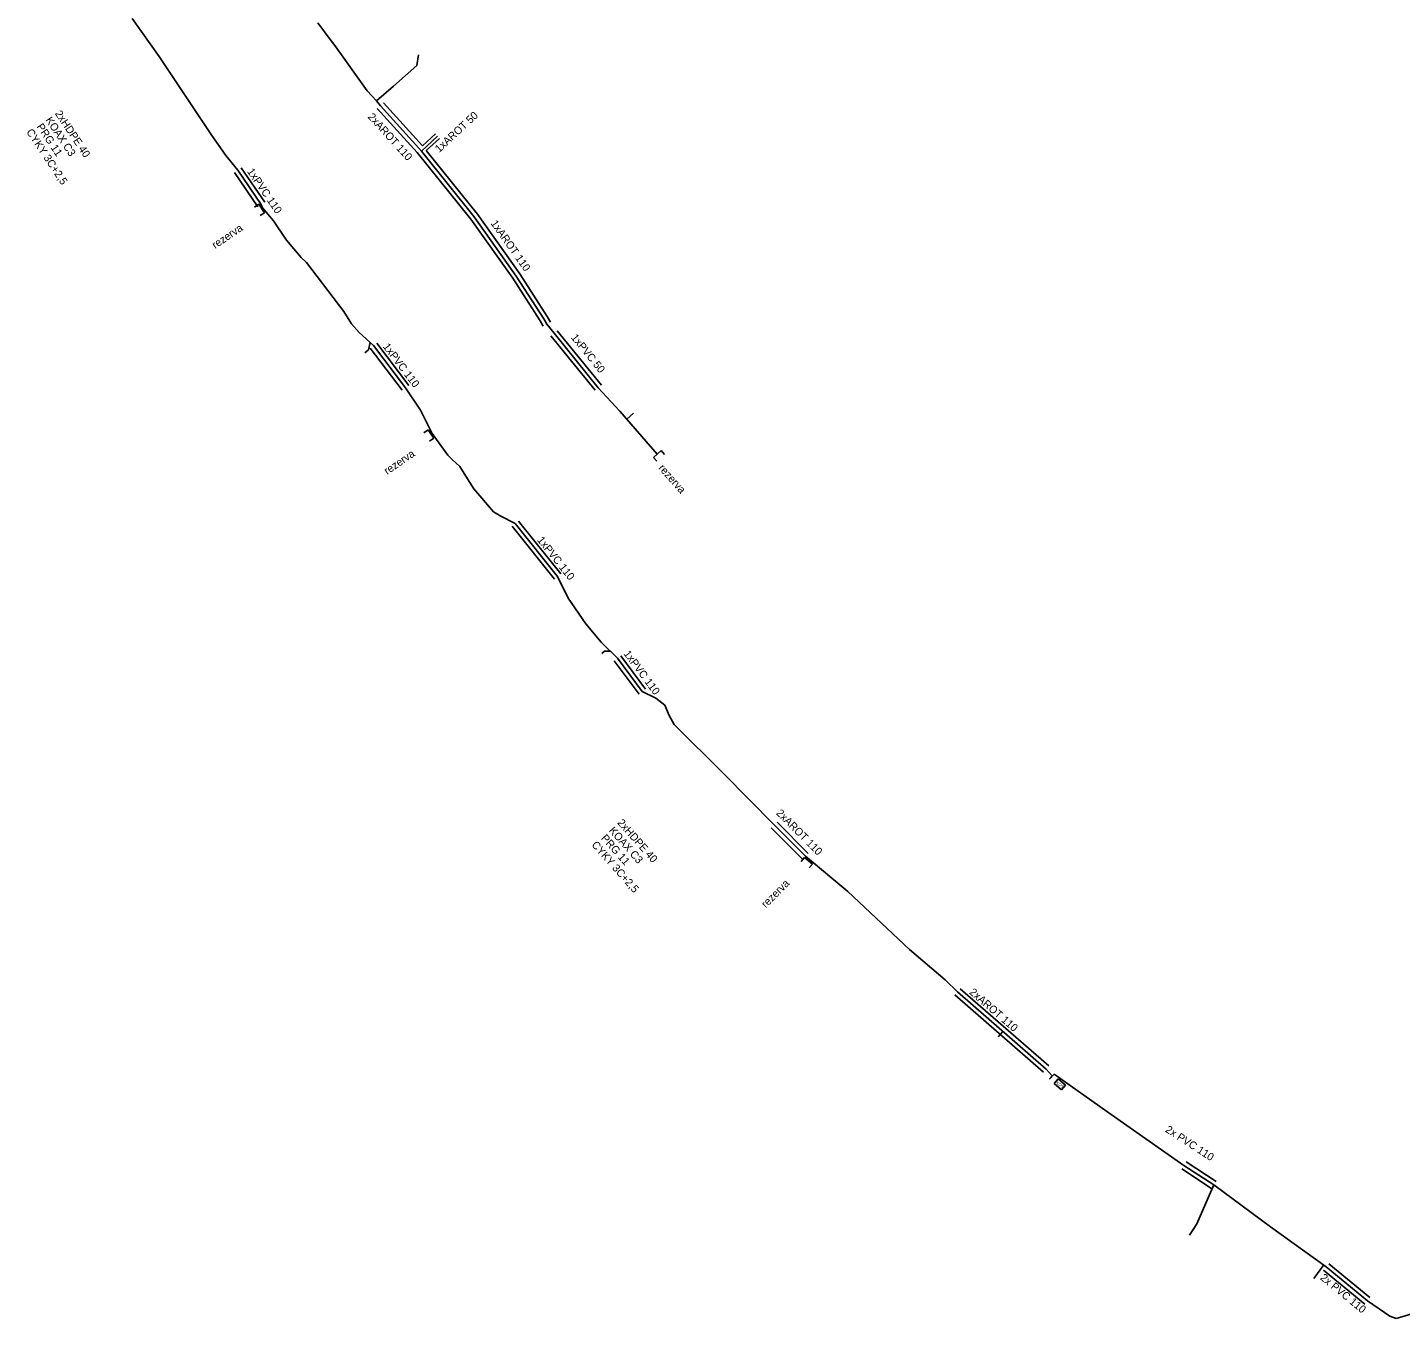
# Model space of a CAD drawing. Extents: x -651943 to -618711, y -1138561 to -1100552.
# Drawn here: x -649125.1 to -648991.6, y -1111942.1 to -1111816.6 of the extents above; entities that cross this region are included whole.
import ezdxf

# ---------------------------------------------------------------- set-up
doc = ezdxf.new("R2010")
doc.units = 0
doc.layers.add('KT trasa', color=7, linetype='Continuous')
doc.layers.add('KT zařízení', color=7, linetype='Continuous')

# ---------------------------------------------------------------- blocks, each defined once
blk = doc.blocks.new('TVREZ')
at = {"layer": 'KT zařízení'}
for p, q in [((-0.05, 0.05), (0, 0.05)), ((0, -0.05), (0, 0.05)), ((-0.05, -0.05), (0, -0.05))]:
    blk.add_line(p, q, dxfattribs=at)

msp = doc.modelspace()

# ---------------------------------------------------------------- linework, layer by layer
at = {"layer": 'KT trasa'}
for p, q in [((-649114.88, -1111815.74), (-649112.25, -1111819.43)), ((-649095.65, -1111817.77), (-649096.85, -1111816.15)), ((-649095.18, -1111818.37), (-649095.65, -1111817.77)), ((-649092.03, -1111822.77), (-649095.18, -1111818.37)), ((-649112.25, -1111819.43), (-649107.21, -1111827.01)), ((-649087.2, -1111820.3), (-649087.04, -1111819.26)), ((-649089.47, -1111822.32), (-649087.2, -1111820.3)), ((-649091.13, -1111823.75), (-649092.03, -1111822.77)), ((-649091.13, -1111823.75), (-649089.47, -1111822.32)), ((-649090.76, -1111824.21), (-649091.13, -1111823.75)), ((-649087.02, -1111828.33), (-649090.76, -1111824.21)), ((-649107.21, -1111827.01), (-649105.78, -1111829.06)), ((-649086.77, -1111828.62), (-649085.21, -1111827.18)), ((-649105.78, -1111829.06), (-649104.61, -1111830.48)), ((-649086.77, -1111828.62), (-649087.02, -1111828.33)), ((-649081.63, -1111835), (-649086.77, -1111828.62)), ((-649104.61, -1111830.48), (-649102.33, -1111833.81)), ((-649102.33, -1111833.81), (-649102.21, -1111834.15)), ((-649102.21, -1111834.15), (-649101.15, -1111835.39)), ((-649101.15, -1111835.39), (-649099.87, -1111837.28)), ((-649077.55, -1111840.77), (-649081.63, -1111835)), ((-649099.87, -1111837.28), (-649098.46, -1111838.95)), ((-649098.46, -1111838.95), (-649097.94, -1111839.46)), ((-649097.94, -1111839.46), (-649094.3, -1111844.21)), ((-649074.88, -1111844.91), (-649077.55, -1111840.77)), ((-649094.3, -1111844.21), (-649093.55, -1111845.42)), ((-649093.55, -1111845.42), (-649092.81, -1111846.24)), ((-649074.58, -1111845.44), (-649074.88, -1111844.91)), ((-649073.87, -1111846.33), (-649074.58, -1111845.44)), ((-649092.81, -1111846.24), (-649091.43, -1111847.52)), ((-649069.58, -1111851.62), (-649073.87, -1111846.33)), ((-649091.91, -1111847.95), (-649092.28, -1111848.23)), ((-649091.74, -1111847.23), (-649091.91, -1111847.95)), ((-649091.43, -1111847.52), (-649088.32, -1111851.63)), ((-649088.32, -1111851.63), (-649086.87, -1111853.79)), ((-649067.49, -1111853.89), (-649069.58, -1111851.62)), ((-649086.87, -1111853.79), (-649085.73, -1111856.07)), ((-649063.84, -1111858.06), (-649067.49, -1111853.89)), ((-649066.81, -1111854.67), (-649066.15, -1111854.09)), ((-649085.73, -1111856.07), (-649084.21, -1111858.16)), ((-649084.21, -1111858.16), (-649083.77, -1111858.59)), ((-649083.77, -1111858.59), (-649083.04, -1111859.26)), ((-649083.04, -1111859.26), (-649082.44, -1111860.22)), ((-649082.44, -1111860.22), (-649081.68, -1111861.43)), ((-649081.68, -1111861.43), (-649079.77, -1111863.67)), ((-649079.77, -1111863.67), (-649079.05, -1111864.1)), ((-649077.64, -1111864.83), (-649079.05, -1111864.1)), ((-649077.64, -1111864.83), (-649073.53, -1111869.96)), ((-649073.53, -1111869.96), (-649072.51, -1111872.07)), ((-649072.51, -1111872.07), (-649070.78, -1111874.55)), ((-649070.78, -1111874.55), (-649069.29, -1111876.35)), ((-649069.29, -1111876.35), (-649067.71, -1111877.91)), ((-649069.22, -1111877.44), (-649068.97, -1111877.23)), ((-649068.41, -1111877.22), (-649068.97, -1111877.23)), ((-649065.29, -1111881.15), (-649067.71, -1111877.91)), ((-649063.98, -1111881.78), (-649065.29, -1111881.15)), ((-649063.09, -1111882.48), (-649063.98, -1111881.78)), ((-649062.69, -1111883.48), (-649063.09, -1111882.48)), ((-649062.19, -1111884.36), (-649062.69, -1111883.48)), ((-649057.41, -1111889.12), (-649062.19, -1111884.36)), ((-649052.47, -1111894.11), (-649057.41, -1111889.12)), ((-649049.43, -1111897.16), (-649052.47, -1111894.11)), ((-649045.32, -1111900.57), (-649049.43, -1111897.16)), ((-649039.32, -1111906.23), (-649045.32, -1111900.57)), ((-649035.84, -1111909.16), (-649039.32, -1111906.23)), ((-649034.66, -1111910.33), (-649035.84, -1111909.16)), ((-649026.02, -1111917.83), (-649034.66, -1111910.33)), ((-649030.24, -1111914.17), (-649030.71, -1111914.7)), ((-649026.02, -1111917.83), (-649025.43, -1111918.48)), ((-649025.43, -1111918.48), (-649025.71, -1111918.79)), ((-649025.26, -1111918.32), (-649025.7, -1111918.81)), ((-649020.03, -1111922.03), (-649025.26, -1111918.32)), ((-649012.63, -1111927.2), (-649020.03, -1111922.03)), ((-649009.72, -1111929.09), (-649012.63, -1111927.2)), ((-649009.72, -1111929.09), (-649011.37, -1111932.88)), ((-649004.23, -1111933.18), (-649009.72, -1111929.09)), ((-649011.37, -1111932.88), (-649012.09, -1111933.98)), ((-648998.81, -1111937.06), (-649004.23, -1111933.18)), ((-648999.04, -1111936.86), (-648999.99, -1111938.19)), ((-648994.8, -1111940.36), (-648998.81, -1111937.06)), ((-648992.63, -1111941.85), (-648994.8, -1111940.36)), ((-648989.94, -1111941.45), (-648992, -1111942.08)), ((-648992, -1111942.08), (-648992.63, -1111941.85))]:
    msp.add_line(p, q, dxfattribs=at)
at = {"layer": 'KT zařízení'}
for p, q in [((-649086.67, -1111828.12), (-649090.46, -1111823.94)), ((-649086.67, -1111828.12), (-649090.46, -1111823.94)), ((-649087.18, -1111828.75), (-649091.06, -1111824.48)), ((-649087.18, -1111828.75), (-649091.06, -1111824.48)), ((-649086.67, -1111828.12), (-649085.4, -1111826.95)), ((-649086.67, -1111828.12), (-649085.4, -1111826.95)), ((-649086.29, -1111828.58), (-649085.02, -1111827.41)), ((-649086.29, -1111828.58), (-649085.02, -1111827.41)), ((-649081.95, -1111835.24), (-649087.18, -1111828.75)), ((-649081.95, -1111835.24), (-649087.18, -1111828.75)), ((-649081.31, -1111834.76), (-649086.29, -1111828.58)), ((-649081.31, -1111834.76), (-649086.29, -1111828.58)), ((-649104.94, -1111830.71), (-649102.66, -1111834.04)), ((-649104.28, -1111830.25), (-649102, -1111833.58)), ((-649077.21, -1111840.56), (-649081.31, -1111834.76)), ((-649077.21, -1111840.56), (-649081.31, -1111834.76)), ((-649077.89, -1111840.98), (-649081.95, -1111835.24)), ((-649077.89, -1111840.98), (-649081.95, -1111835.24)), ((-649075.23, -1111845.11), (-649077.89, -1111840.98)), ((-649075.23, -1111845.11), (-649077.89, -1111840.98)), ((-649074.53, -1111844.71), (-649077.21, -1111840.56)), ((-649074.53, -1111844.71), (-649077.21, -1111840.56)), ((-649074.93, -1111845.64), (-649075.23, -1111845.11)), ((-649074.93, -1111845.64), (-649075.23, -1111845.11)), ((-649074.23, -1111845.24), (-649074.53, -1111844.71)), ((-649074.23, -1111845.24), (-649074.53, -1111844.71)), ((-649069.89, -1111851.87), (-649074.18, -1111846.58)), ((-649069.89, -1111851.87), (-649074.18, -1111846.58)), ((-649069.27, -1111851.37), (-649073.56, -1111846.08)), ((-649069.27, -1111851.37), (-649073.56, -1111846.08)), ((-649091.75, -1111847.76), (-649088.64, -1111851.87)), ((-649091.11, -1111847.28), (-649088, -1111851.39)), ((-649077.95, -1111865.08), (-649073.84, -1111870.21)), ((-649077.33, -1111864.58), (-649073.22, -1111869.71)), ((-649064.97, -1111880.91), (-649067.39, -1111877.67)), ((-649065.61, -1111881.39), (-649068.03, -1111878.15)), ((-649049.71, -1111897.44), (-649052.75, -1111894.39)), ((-649049.15, -1111896.88), (-649052.19, -1111893.83)), ((-649026.28, -1111918.13), (-649034.92, -1111910.63)), ((-649025.76, -1111917.53), (-649034.4, -1111910.03)), ((-649024.85, -1111918.79), (-649025.25, -1111919.24)), ((-649024.14, -1111919.4), (-649024.85, -1111918.79)), ((-649024.53, -1111919.86), (-649025.25, -1111919.24)), ((-649024.14, -1111919.4), (-649024.53, -1111919.86)), ((-649009.5, -1111928.75), (-649012.41, -1111926.86)), ((-649009.94, -1111929.43), (-649012.85, -1111927.54)), ((-648995.05, -1111940.67), (-648999.06, -1111937.37)), ((-648994.55, -1111940.05), (-648998.56, -1111936.75))]:
    msp.add_line(p, q, dxfattribs=at)

# ---------------------------------------------------------------- block references
for p, xscale, yscale, rotation in [((-649102.3, -1111834.2), 9.999973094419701, 9.999973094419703, 34.209692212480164), ((-649085.84, -1111856.12), 9.999981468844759, 9.999981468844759, 34.52642772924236), ((-649063.84, -1111858.06), 10.000009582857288, 10.000009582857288, 131.73215976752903), ((-649063.84, -1111858.06), 10.000009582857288, 10.000009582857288, 131.73215976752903), ((-649049.13, -1111897.59), 9.999995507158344, 9.999995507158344, 49.7576097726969)]:
    msp.add_blockref('TVREZ', p, dxfattribs=dict(at, xscale=xscale, yscale=yscale, rotation=rotation))

# ---------------------------------------------------------------- texts
for s, height, rotation, p in [('KOAX C3', 0.75, 303.6202, (-649123.35, -1111825.6)), ('2xHDPE 40', 0.75, 303.6202, (-649122.43, -1111824.97)), ('2xAROT 110', 0.75, 312.2348, (-649092.03, -1111825.33)), ('2xAROT 110', 0.75, 312.2348, (-649092.03, -1111825.33)), ('1xAROT 50', 0.75, 42.7109, (-649085.04, -1111828.81)), ('1xAROT 50', 0.75, 42.7109, (-649085.04, -1111828.81)), ('CYKY 3C+2,5', 0.75, 303.6202, (-649125.21, -1111826.76)), ('PRG 11', 0.75, 303.6202, (-649124.21, -1111826.24)), ('1xPVC 110', 0.75, 304.3988, (-649103.75, -1111830.6)), ('rezerva', 0.75, 34.3256, (-649106.82, -1111838.15)), ('1xAROT 110', 0.75, 305.2637, (-649080.07, -1111835.65)), ('1xAROT 110', 0.75, 305.2637, (-649080.07, -1111835.65)), ('1xPVC 50', 0.75, 309.0408, (-649072.27, -1111846.76)), ('1xPVC 50', 0.75, 309.0408, (-649072.27, -1111846.76)), ('1xPVC 110', 0.75, 307.1145, (-649090.55, -1111847.63)), ('rezerva', 0.75, 34.4849, (-649090.09, -1111860.1)), ('rezerva', 0.75, 311.4361, (-649063.77, -1111859.46)), ('rezerva', 0.75, 311.4361, (-649063.77, -1111859.46)), ('1xPVC 110', 0.75, 308.7006, (-649075.56, -1111866.44)), ('1xPVC 110', 0.75, 306.7566, (-649067.15, -1111877.48)), ('2xHDPE 40', 0.75, 311.5316, (-649067.77, -1111893.93)), ('2xAROT 110', 0.75, 314.9059, (-649052.33, -1111893.02)), ('PRG 11', 0.75, 311.5316, (-649069.35, -1111895.43)), ('KOAX C3', 0.75, 311.5316, (-649068.59, -1111894.69)), ('CYKY 3C+2,5', 0.75, 311.5316, (-649070.27, -1111896.08)), ('rezerva', 0.75, 45.2682, (-649053.28, -1111902.23)), ('2xAROT 110', 0.75, 319.0402, (-649033.56, -1111910.46)), ('KOS', 0.282, 320.6134, (-649025.09, -1111919.2)), ('2x PVC 110', 0.75, 326.9969, (-649014.51, -1111923.89)), ('2x PVC 110', 0.75, 320.5476, (-648999.45, -1111938.22))]:
    msp.add_text(s, height=height, rotation=rotation, dxfattribs=at).set_placement(p)

doc.saveas('drawing.dxf')
